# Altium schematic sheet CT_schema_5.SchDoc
size 221 x 258 mm
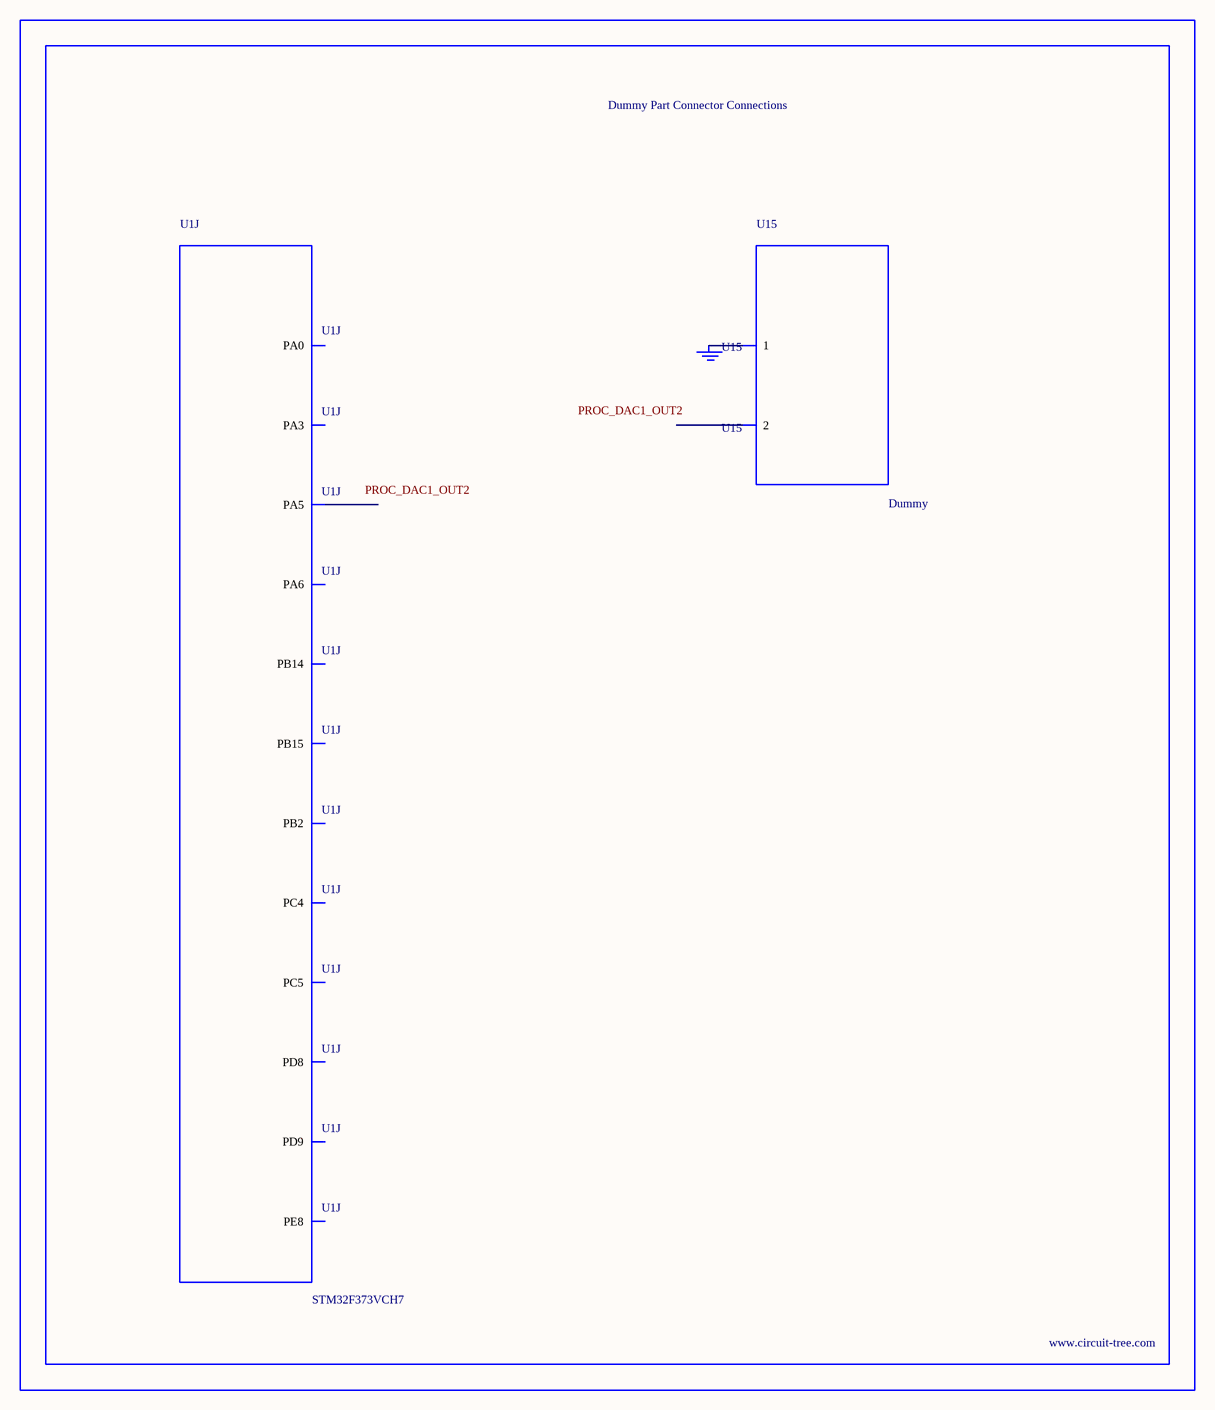
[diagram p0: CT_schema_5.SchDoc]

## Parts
BORDER4  (no value)
GND_INSTANCE_4_0  (no value)
U1  STM32F373VCH7  [UFBGA100]  (part J of 10)
U15  Dummy  [DUMMY_PACKAGE_149]

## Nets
NetGND_INSTANCE_4_0_0: GND_INSTANCE_4_0.0(GND) U15.1

Not connected (* = marked no-connect by the designer): U1 K4(PA5) K5(PC4) K8(PD9) K9(PD8) K10(PB15) K11(PB14) L2(PA0) L3(PA3) L4(PA6) L5(PC5) L6(PB2) L7(PE8); U15 2

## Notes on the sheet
- Labels drawn without touching a wire or pin: PROC_DAC1_OUT2

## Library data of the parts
BORDER4 = BORDER_PAGE4
GND_INSTANCE_4_0 = GND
